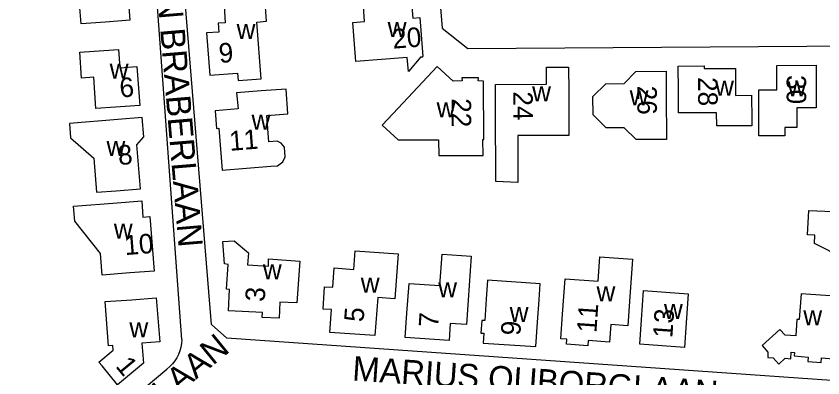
# Model space of a CAD drawing. Extents: x 156721 to 158827, y 386657 to 388950.
# Drawn here: x 158250 to 158415.3, y 387526.8 to 387600.8 of the extents above; entities that cross this region are included whole.
import ezdxf

# ---------------------------------------------------------------- set-up
doc = ezdxf.new("R2010")
doc.units = 0
for name, color, linetype in [('BLT_Basislijn', 7, 'Continuous'), ('BLT_Bebouwing', 7, 'Continuous'), ('BLT_Centroide', 7, 'Continuous'), ('BLT_Huisnummer', 7, 'Continuous'), ('BLT_Straatnaam', 7, 'Continuous')]:
    doc.layers.add(name, color=color, linetype=linetype)

msp = doc.modelspace()

# ---------------------------------------------------------------- linework, layer by layer
at = {"layer": 'BLT_Basislijn'}
for p, q in [((158283.92, 387534.66), (158277.84, 387617.97)), ((158236.7, 387491.73), (158280.86, 387528.64))]:
    msp.add_line(p, q, dxfattribs=at)
for points in [[(158331.61, 387684.16), (158330.27, 387682.97), (158337.29, 387598.34), (158342.49, 387594.21), (158431.88, 387594.8), (158432.5, 387594.66), (158434.94, 387592.24), (158434.85, 387566.34), (158432.92, 387555.36), (158430.15, 387548.17), (158421.36, 387530.67), (158420.31, 387528.76), (158417.02, 387526.27), (158293.15, 387534.97), (158290, 387537.72), (158280.9, 387649.05), (158280.63, 387649.25), (158242.83, 387649.3)], [(158283.92, 387534.66), (158283.87, 387533.88), (158283.74, 387533.12), (158283.54, 387532.37), (158283.26, 387531.64), (158282.91, 387530.95), (158282.49, 387530.29), (158282.01, 387529.69), (158281.46, 387529.13), (158280.86, 387528.64)]]:
    msp.add_lwpolyline(points, dxfattribs=at)
at = {"layer": 'BLT_Bebouwing'}
for points in [[(158268.27, 387599.63), (158263.27, 387599.23), (158262.48, 387609.13), (158258.65, 387608.83), (158258.34, 387612.82), (158261.34, 387613.06), (158266.32, 387613.46), (158266.61, 387609.55), (158272.48, 387609.99), (158273.25, 387600.02), (158268.27, 387599.63)], [(158300.15, 387588), (158299.26, 387599.62), (158301.29, 387599.78), (158301, 387603.61), (158297.57, 387603.35), (158292.59, 387602.97), (158292.83, 387599.47), (158291.34, 387599.37), (158291.51, 387597.58), (158288.99, 387597.41), (158289.65, 387588.73), (158295.35, 387589.17), (158295.47, 387587.64), (158300.15, 387588)], [(158330.34, 387589.52), (158330.12, 387592.36), (158319.58, 387591.56), (158318.97, 387599.54), (158321.37, 387599.72), (158321.14, 387602.8), (158325.98, 387603.16), (158330.96, 387603.54), (158331.22, 387600.43), (158332.67, 387600.56), (158333.28, 387592.58), (158333.09, 387592.36), (158332.89, 387592.53), (158330.34, 387589.52)], [(158270.31, 387582.22), (158266.33, 387581.93), (158265.87, 387588.33), (158263.38, 387588.15), (158262.99, 387593.45), (158265.97, 387593.67), (158270.96, 387594.03), (158271.23, 387590.28), (158274.71, 387590.53), (158275.3, 387582.58), (158270.31, 387582.22)], [(158336.56, 387572.31), (158345.66, 387572.35), (158345.58, 387575.59), (158345.78, 387575.58), (158345.73, 387587.55), (158344.65, 387587.58), (158344.73, 387588.24), (158341.29, 387588.21), (158341.33, 387587.62), (158339.51, 387587.54), (158336.24, 387590.56), (158328.25, 387582.01), (158324.99, 387578.54), (158328.24, 387575.5), (158336.54, 387575.54), (158336.56, 387572.31)], [(158363.18, 387585.41), (158363.2, 387576.4), (158352.73, 387576.38), (158352.75, 387566.77), (158348.26, 387566.97), (158348.19, 387581.82), (158348.16, 387586.82), (158358.66, 387586.9), (158358.63, 387590.39), (158363.17, 387590.41), (158363.18, 387585.41)], [(158383.18, 387584.59), (158383.21, 387575.61), (158376.99, 387575.58), (158374.54, 387577.99), (158370.84, 387578), (158368.17, 387580.64), (158368.14, 387584.38), (158370.79, 387587.01), (158374.53, 387587.03), (158376.97, 387589.53), (158383.16, 387589.58), (158383.18, 387584.59)], [(158400.7, 387579.63), (158400.7, 387578.42), (158393.5, 387578.38), (158393.48, 387581.07), (158385.69, 387581.02), (158385.66, 387585.63), (158385.63, 387590.63), (158390.94, 387590.66), (158390.93, 387590.09), (158397.36, 387590.14), (158397.37, 387584.62), (158400.67, 387584.63), (158400.7, 387579.63)], [(158413.9, 387585.79), (158413.91, 387582.06), (158409.93, 387582.05), (158409.94, 387578.04), (158407.44, 387578.03), (158407.45, 387576.35), (158402.16, 387576.33), (158402.15, 387580.74), (158402.13, 387585.74), (158405.85, 387585.75), (158405.84, 387590.76), (158413.89, 387590.79), (158413.9, 387585.79)], [(158300.14, 387585.52), (158295.15, 387585.13), (158295.44, 387581.89), (158290.73, 387581.48), (158291.01, 387577.87), (158291.5, 387577.91), (158292.16, 387569.34), (158297.15, 387569.73), (158302.15, 387570.11), (158303.49, 387570.22), (158304.63, 387571.05), (158305.11, 387572.06), (158304.95, 387574.05), (158304.27, 387574.87), (158303.46, 387575.28), (158301.76, 387575.15), (158301.34, 387580.49), (158305.66, 387580.83), (158305.27, 387585.91), (158300.14, 387585.52)], [(158270.83, 387579.69), (158260.87, 387578.9), (158261.09, 387575.91), (158265.89, 387571.78), (158266.46, 387564.8), (158270.45, 387565.12), (158275.43, 387565.53), (158274.72, 387574.48), (158276.1, 387576.11), (158275.81, 387580.09), (158270.83, 387579.69)], [(158273.24, 387548.3), (158267.61, 387547.87), (158267.27, 387552.27), (158261.97, 387558.9), (158261.74, 387561.97), (158270.7, 387562.66), (158275.69, 387563.05), (158275.96, 387559.71), (158277.38, 387559.83), (158278.23, 387548.69), (158273.24, 387548.3)], [(158425.44, 387551.69), (158424.05, 387548.98), (158419.6, 387551.25), (158413.54, 387554.33), (158413.62, 387556.01), (158412.12, 387556.08), (158412.35, 387561.07), (158418.93, 387560.78)], [(158342.56, 387542.71), (158342.21, 387537.72), (158338.93, 387537.95), (158338.69, 387534.46), (158329.69, 387535.11), (158330.05, 387540.1), (158330.48, 387546.15), (158336.81, 387545.71), (158337.25, 387552.15), (158343.19, 387551.74), (158342.56, 387542.71)], [(158375.64, 387542.47), (158375.3, 387537.48), (158371.8, 387537.73), (158371.54, 387534.14), (158367.17, 387534.45), (158367.1, 387533.41), (158362.71, 387533.72), (158362.78, 387534.77), (158361.57, 387534.85), (158361.92, 387539.84), (158362.44, 387547.1), (158369.21, 387546.62), (158369.56, 387551.6), (158376.24, 387551.13), (158375.64, 387542.47)], [(158356.79, 387538.21), (158357.11, 387542.77), (158357.35, 387546.09), (158346.58, 387546.85), (158346.3, 387542.93), (158345.99, 387538.54), (158345.4, 387538.59), (158345.21, 387536), (158345.81, 387535.96), (158345.67, 387533.96), (158356.44, 387533.22), (158356.79, 387538.21)], [(158387.26, 387538.07), (158386.91, 387533.08), (158377.73, 387533.72), (158378.09, 387538.71), (158378.53, 387544.72), (158387.68, 387544.05), (158387.26, 387538.07)], [(158412.81, 387543.89), (158410.82, 387544.04), (158410.43, 387538.75), (158409.93, 387538.79), (158409.69, 387535.44), (158407.51, 387535.6), (158406.47, 387536.75), (158402.8, 387533.43), (158404.01, 387532.09), (158403.97, 387530.97), (158405.06, 387530.94), (158406.23, 387529.66), (158407.52, 387530.84), (158408.7, 387530.76), (158408.79, 387532.08), (158409.44, 387532.03), (158409.39, 387531.31), (158412.26, 387531.1), (158412.19, 387530.17), (158414.92, 387529.97), (158414.99, 387530.9), (158419.16, 387530.6)], [(158417.8, 387543.53), (158412.81, 387543.89)], [(158273.69, 387542.83), (158278.68, 387543.19), (158279.42, 387534.21), (158275.75, 387533.93), (158276.09, 387529.82), (158270.74, 387525.43), (158267.57, 387529.29), (158266.92, 387530.08), (158269.84, 387532.47), (158269.76, 387533.45), (158268.86, 387533.39), (158268.21, 387542.44), (158273.69, 387542.83)]]:
    msp.add_lwpolyline(points, dxfattribs=at)
for points in [[(158292.3, 387554.7), (158294.65, 387554.9), (158297.56, 387552.42), (158297.39, 387549.99), (158301.65, 387549.69), (158301.67, 387551.19), (158308.09, 387550.73), (158307.5, 387542.17), (158303.99, 387542.32), (158303.83, 387539.04), (158300.37, 387539.21), (158300.42, 387540.19), (158293.48, 387540.53), (158293.69, 387544.91), (158293.05, 387544.96), (158293.42, 387550.03), (158292.65, 387550.15)], [(158319.42, 387552.83), (158328.22, 387552.22), (158327.54, 387543), (158324.07, 387543.26), (158323.49, 387535.47), (158314.23, 387536.09), (158314.55, 387540.79), (158312.86, 387540.9), (158313.18, 387545.49), (158314.88, 387545.37), (158315.15, 387549.31), (158319.16, 387549.03)]]:
    msp.add_lwpolyline(points, close=True, dxfattribs=at)

# ---------------------------------------------------------------- texts
at = {"layer": 'BLT_Centroide'}
for p in [(158326.09, 387596.53), (158295.14, 387596.16), (158269.14, 387588.02), (158355.69, 387583.39), (158393.17, 387584.53), (158408.02, 387584.41), (158375.67, 387582.59), (158336.12, 387580.12), (158298.2, 387577.59), (158268.48, 387572.23), (158269.98, 387555.33), (158300.52, 387547), (158320.58, 387544.25), (158336.44, 387543.31), (158368.88, 387542.5), (158382.7, 387538.89), (158351.09, 387538.25), (158411.25, 387537.59), (158273.17, 387535.11)]:
    msp.add_text('w', height=4, dxfattribs=at).set_placement(p)
at = {"layer": 'BLT_Huisnummer'}
for s, rotation, p in [('20', 4.326, (158327.19, 387594.17)), ('9', 4.3826, (158291.63, 387591.24)), ('6', 4.1754, (158271.28, 387584.18)), ('28', 270.3358, (158389.68, 387588.36)), ('30', 270.1375, (158407.83, 387588.78)), ('26', 270.1978, (158377.24, 387586.6)), ('24', 270.298, (158351.81, 387585.43)), ('22', 270.2465, (158339.19, 387584.04)), ('11', 4.4364, (158293.77, 387573.27)), ('8', 4.6466, (158270.99, 387570.36)), ('10', 4.4163, (158272.29, 387551.94)), ('3', 86.0651, (158300.87, 387542.31)), ('11', 86.067, (158368.85, 387535.97)), ('5', 85.7685, (158321.14, 387538.16)), ('7', 85.9862, (158336.42, 387537.07)), ('13', 85.9862, (158384.4, 387534.9)), ('9', 85.9634, (158353.25, 387535.39)), ('1', 309.4007, (158270.2, 387529.18))]:
    msp.add_text(s, height=4, rotation=rotation, dxfattribs=at).set_placement(p)
at = {"layer": 'BLT_Straatnaam'}
for s, rotation, p in [('GERRIT DEN BRABERLAAN', 274.8139, (158275.87, 387641.12)), ('MARIUS OUBORGLAAN', 39.24, (158235.88, 387484.86)), ('MARIUS OUBORGLAAN', 356.1063, (158318.74, 387526.32))]:
    msp.add_text(s, height=5, rotation=rotation, dxfattribs=at).set_placement(p)

doc.saveas('drawing.dxf')
